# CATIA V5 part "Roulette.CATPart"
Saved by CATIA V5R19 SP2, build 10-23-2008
Part number: Roulette
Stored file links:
  D:\SCHOOL\FRANCE\BANC_POUTRE_EN_MOUSSE\Roulette.CATPart

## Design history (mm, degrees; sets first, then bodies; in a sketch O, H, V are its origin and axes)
AxisSystem1: origin (0, 0, 0), X (1, 0, 0), Y (0, 1, 0), Z (0, 0, 1)
Body1 (main body)
  Sketch1 on YZ plane of AxisSystem1, origin (0, 0, 0), H (0, 1, 0), V (0, 0, 1)
    circle A1 centre (0, 0) radius 4
    circle A2 centre (0, 0) radius 7.5
    radius A2 = 7.5
    radius A1 = 4
  Pad1: profile Sketch1, direction (1, 0, 0), length 8
  Fillet1: radius 1, on edge [face of Pad1 from Sketch1.A2 | end face of Pad1]
  Fillet2: radius 1, on edge [start face of Pad1 | face of Pad1 from Sketch1.A2]
  Fillet3: radius 1, on edge [end face of Pad1 | face of Pad1 from Sketch1.A1]
  Fillet4: radius 1, on edge [face of Pad1 from Sketch1.A1 | start face of Pad1]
